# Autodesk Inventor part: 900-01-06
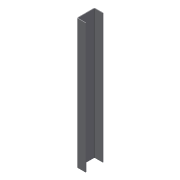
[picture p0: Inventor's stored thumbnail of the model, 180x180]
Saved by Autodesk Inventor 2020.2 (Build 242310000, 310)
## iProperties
Created: 2015-10
Part Number: 900-01-06
Material: Ogólny
Document SubType Name: Konstrukcja blachowa
Designer: F.Stasiak
Density: 1 g/cm^3
Sheet Metal Rule: Domyślny_mm
Appearance: Domyślna
Catalog Web Link: www.expertbooks.pl
Manager: www.cadconsulting.pl
Company: Fabian Stasiak CAD Consulting
Author: F.Stasiak
Subject: Zbiór ćwiczeń. Autodesk Inventor 2020. Kurs Professional
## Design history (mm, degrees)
node "Kołnierz z profilu1"
  sketch "Szkic1"
    geometry: L1 (60, -60)-(0, -60); L2 (0, -60)-(0, 60); L3 (0, 60)-(60, 60); 2 further points
    constraints: 6 end point, 2 perpendicular, 1 coincident, 1 horizontal, 1 midpoint, 1 parallel
    dimensions: "d0" = 120 distance of L1.end L2.end; "d1" = 60 distance of L1.start L1.end
node "Bryła1"
feature "Płyta1" dims "d2" = 4.5 (= SzerokośćGięciaPodcięcia), "d3" = 2.25 (= GłębokośćGięciaPodcięcia), "d4" = 9 (= MinimalnaPozostałość), "d5" = 4.5 (= PromieńGięcia), "d6" = 870, "d7" = 4.5 (= PromieńGięcia), "d8" = 3.5, "d9" = 18 (= RozmiarPodcięciaNarożnika), "d10" = 4.5 (= Wielk_odstępu), "d11" = 4.5 (= Rozmiar_promienia_Jacobiego), "d12" = 4.5 (= Grubość), "OdstępPołączenia" = 0.01
feature "Gięcie1" dims "d2" = 4.5 (= SzerokośćGięciaPodcięcia), "d3" = 2.25 (= GłębokośćGięciaPodcięcia), "d4" = 9 (= MinimalnaPozostałość), "d5" = 4.5 (= PromieńGięcia), "d7" = 4.5 (= PromieńGięcia), "d8" = 3.5, "d12" = 4.5 (= Grubość), "OdstępPołączenia" = 0.01
feature "Narożnik1" dims "d8" = 3.5, "d9" = 18 (= RozmiarPodcięciaNarożnika), "d10" = 4.5 (= Wielk_odstępu), "d11" = 4.5 (= Rozmiar_promienia_Jacobiego)
other parameters: "Grubość" = 4.5, "WspółczynnikK" = 4.4, "PromieńGięcia" = 4.5 (= Grubość), "SzerokośćGięciaPodcięcia" = 4.5 (= Grubość), "GłębokośćGięciaPodcięcia" = 2.25 (= 0.5 x Grubość), "RozmiarPodcięciaNarożnika" = 18 (= 4 x Grubość), "MinimalnaPozostałość" = 9 (= 2 x Grubość), "PromieńPrzejścia" = 4.5 (= PromieńGięcia), "Rozmiar_promienia_Jacobiego" = 4.5 (= PromieńGięcia), "Wielk_odstępu" = 4.5 (= Grubość)
